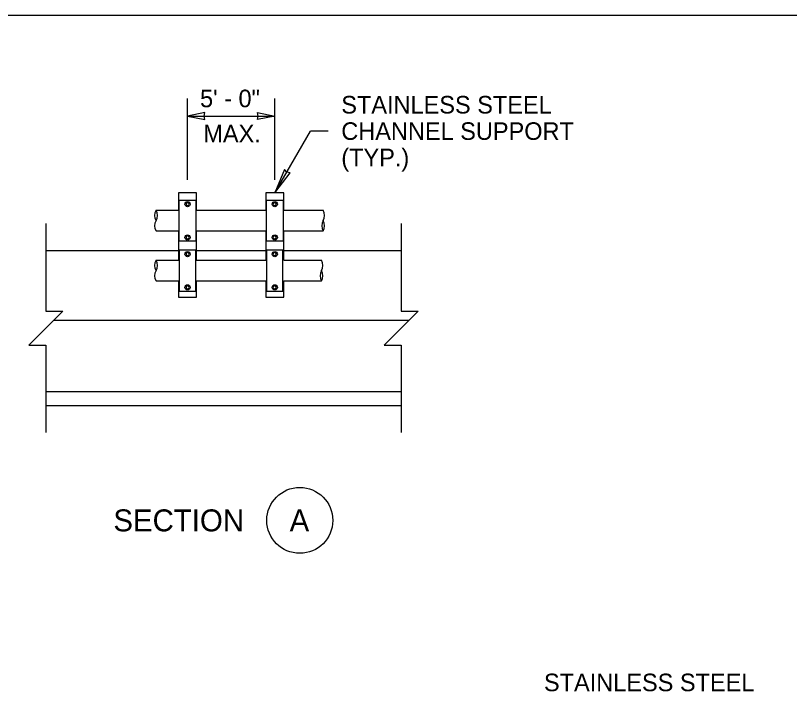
# Model space of a CAD drawing. Extents: x 99862 to 103151, y 100000 to 102076.
# Drawn here: x 100730 to 101434, y 101458 to 102076 of the extents above; entities that cross this region are included whole.
import ezdxf

# ---------------------------------------------------------------- set-up
doc = ezdxf.new("R2010")
doc.units = 0
for name, color, linetype in [('Level 1', 7, 'Continuous'), ('Level 10', 7, 'Continuous'), ('Level 15', 7, 'Continuous'), ('Level 2', 7, 'Continuous'), ('Level 20', 7, 'Continuous'), ('Level 4', 7, 'Continuous'), ('Level 5', 7, 'Continuous'), ('Level 9', 7, 'Continuous')]:
    doc.layers.add(name, color=color, linetype=linetype)

msp = doc.modelspace()

# ---------------------------------------------------------------- linework, layer by layer
at = {"layer": 'Level 1'}
msp.add_lwpolyline([(99862, 99999.5), (103151, 99999.5), (103151, 102075.5), (99862, 102075.5)], close=True, dxfattribs=at)
for points in [[(100894.9, 101898.28), (100894.9, 101913.98), (100878.6, 101913.98), (100878.6, 101898.28)], [(100974.26, 101898.28), (100974.26, 101913.98), (100957.97, 101913.98), (100957.97, 101898.28)], [(100878.6, 101879.38), (100878.6, 101852.81)], [(100894.9, 101852.81), (100894.9, 101879.38)], [(100957.97, 101879.38), (100957.97, 101852.81)], [(100974.26, 101852.81), (100974.26, 101879.38)], [(100878.6, 101833.91), (100878.6, 101819.05), (100894.9, 101819.05), (100894.9, 101833.91)], [(100957.97, 101833.91), (100957.97, 101819.05), (100974.26, 101819.05), (100974.26, 101833.91)]]:
    msp.add_lwpolyline(points, dxfattribs=at)
at = {"layer": 'Level 10'}
for p, q in [((100757.79, 101861.52), (100878.6, 101861.52)), ((100894.9, 101861.52), (100957.97, 101861.52)), ((100974.26, 101861.52), (101081, 101861.52)), ((100764.87, 101798.11), (101088.08, 101798.11)), ((100757.79, 101733.31), (101081, 101733.31)), ((100757.79, 101720.53), (101081, 101720.53))]:
    msp.add_line(p, q, dxfattribs=at)
at = {"layer": 'Level 15'}
for p, q in [((100886.75, 101925.98), (100886.75, 101999.98)), ((100966.11, 101925.98), (100966.11, 101999.98)), ((100886.75, 101983.98), (100966.11, 101983.98)), ((100966.11, 101913.98), (100998.61, 101970.27)), ((101014.61, 101970.27), (100998.61, 101970.27))]:
    msp.add_line(p, q, dxfattribs=at)
for points in [[(100886.75, 101983.98), (100902.48, 101980.9), (100901.75, 101983.98), (100902.48, 101987.07)], [(100966.11, 101983.98), (100950.39, 101980.9), (100951.12, 101983.98), (100950.39, 101987.07)], [(100966.11, 101913.98), (100980.11, 101932.26), (100977, 101932.84), (100974.94, 101935.25)]]:
    msp.add_lwpolyline(points, close=True, dxfattribs=at)
for points in [[(100757.79, 101886.06), (100757.79, 101806.51), (100773.27, 101806.51), (100742.3, 101775.54), (100757.79, 101775.54), (100757.79, 101696)], [(101081, 101886.06), (101081, 101806.51), (101096.48, 101806.51), (101065.51, 101775.54), (101081, 101775.54), (101081, 101696)]]:
    msp.add_lwpolyline(points, dxfattribs=at)
at = {"layer": 'Level 2'}
for points in [[(100879.27, 101907.28), (100894.23, 101907.28), (100894.23, 101870.07), (100879.27, 101870.07)], [(100958.63, 101907.28), (100973.6, 101907.28), (100973.6, 101870.07), (100958.63, 101870.07)], [(100879.22, 101824.6), (100894.19, 101824.6), (100894.19, 101861.81), (100879.22, 101861.81)], [(100958.59, 101824.6), (100973.55, 101824.6), (100973.55, 101861.81), (100958.59, 101861.81)]]:
    msp.add_lwpolyline(points, close=True, dxfattribs=at)
at = {"layer": 'Level 20'}
msp.add_circle((100988.85, 101616), 30, dxfattribs=at)
at = {"layer": 'Level 4'}
for points in [[(100885.21, 101903.8), (100885.97, 101902.49), (100887.48, 101902.49), (100888.24, 101903.8), (100887.48, 101905.11), (100885.97, 101905.11)], [(100964.57, 101903.8), (100965.33, 101902.49), (100966.84, 101902.49), (100967.6, 101903.8), (100966.84, 101905.11), (100965.33, 101905.11)], [(100885.24, 101873.51), (100886, 101872.2), (100887.51, 101872.2), (100888.27, 101873.51), (100887.51, 101874.82), (100886, 101874.82)], [(100964.6, 101873.51), (100965.36, 101872.2), (100966.87, 101872.2), (100967.63, 101873.51), (100966.87, 101874.82), (100965.36, 101874.82)], [(100885.24, 101858.33), (100885.99, 101857.02), (100887.51, 101857.02), (100888.27, 101858.33), (100887.51, 101859.65), (100885.99, 101859.65)], [(100964.6, 101858.33), (100965.36, 101857.02), (100966.87, 101857.02), (100967.63, 101858.33), (100966.87, 101859.65), (100965.36, 101859.65)], [(100885.24, 101828.04), (100885.99, 101826.73), (100887.51, 101826.73), (100888.27, 101828.04), (100887.51, 101829.35), (100885.99, 101829.35)], [(100964.6, 101828.04), (100965.36, 101826.73), (100966.87, 101826.73), (100967.63, 101828.04), (100966.87, 101829.35), (100965.36, 101829.35)]]:
    msp.add_lwpolyline(points, close=True, dxfattribs=at)
at = {"layer": 'Level 5'}
for centre in [(100886.72, 101903.8), (100966.09, 101903.8), (100886.75, 101873.51), (100966.11, 101873.51), (100886.75, 101858.33), (100966.11, 101858.33), (100886.75, 101828.04), (100966.11, 101828.04)]:
    msp.add_circle(centre, 2.38, dxfattribs=at)
at = {"layer": 'Level 9'}
for p, q in [((100858.07, 101898.28), (100878.6, 101898.28)), ((100894.9, 101898.28), (100957.97, 101898.28)), ((100974.26, 101898.28), (101010.05, 101898.28)), ((100858.08, 101879.38), (100878.6, 101879.38)), ((100894.9, 101879.38), (100957.97, 101879.38)), ((100974.26, 101879.38), (101010.06, 101879.38)), ((100858.07, 101852.81), (100878.6, 101852.81)), ((100894.9, 101852.81), (100957.97, 101852.81)), ((100974.26, 101852.81), (101008.69, 101852.81)), ((100858.08, 101833.91), (100878.6, 101833.91)), ((100894.9, 101833.91), (100957.97, 101833.91)), ((100974.26, 101833.91), (101008.7, 101833.91))]:
    msp.add_line(p, q, dxfattribs=at)
for centre, start, end in [((100866.25, 101893.56), 150, 210), ((100849.89, 101893.56), 330, 30), ((101001.87, 101893.56), 330, 30), ((100866.25, 101884.12), 150, 210.10645), ((101018.23, 101884.12), 150, 210.10645), ((101001.87, 101884.12), 330, 30), ((100866.25, 101848.09), 150, 210), ((100849.89, 101848.09), 330, 30), ((101000.51, 101848.09), 330, 30), ((100866.25, 101838.65), 150, 210.10645), ((101016.87, 101838.65), 150, 210.10645), ((101000.51, 101838.65), 330, 30)]:
    msp.add_arc(centre, 9.44, start, end, dxfattribs=at)

# ---------------------------------------------------------------- texts
at = {"layer": 'Level 20'}
for s, height, p in [('5\' - 0"', 16, (100898.1, 101991.98)), ('MAX.', 16, (100901.08, 101959.98)), ('SECTION', 20, (100819.26, 101605.98)), ('A', 20, (100979.61, 101606))]:
    msp.add_text(s, height=height, dxfattribs=at).set_placement(p)
for s, p in [('STAINLESS STEEL', (101026.61, 101986.28)), ('CHANNEL SUPPORT', (101026.61, 101962.28)), ('(TYP.)', (101026.61, 101938.28)), ('STAINLESS STEEL', (101211, 101460.52))]:
    msp.add_text(s, height=16, rotation=360, dxfattribs=at).set_placement(p)

doc.saveas('drawing.dxf')
